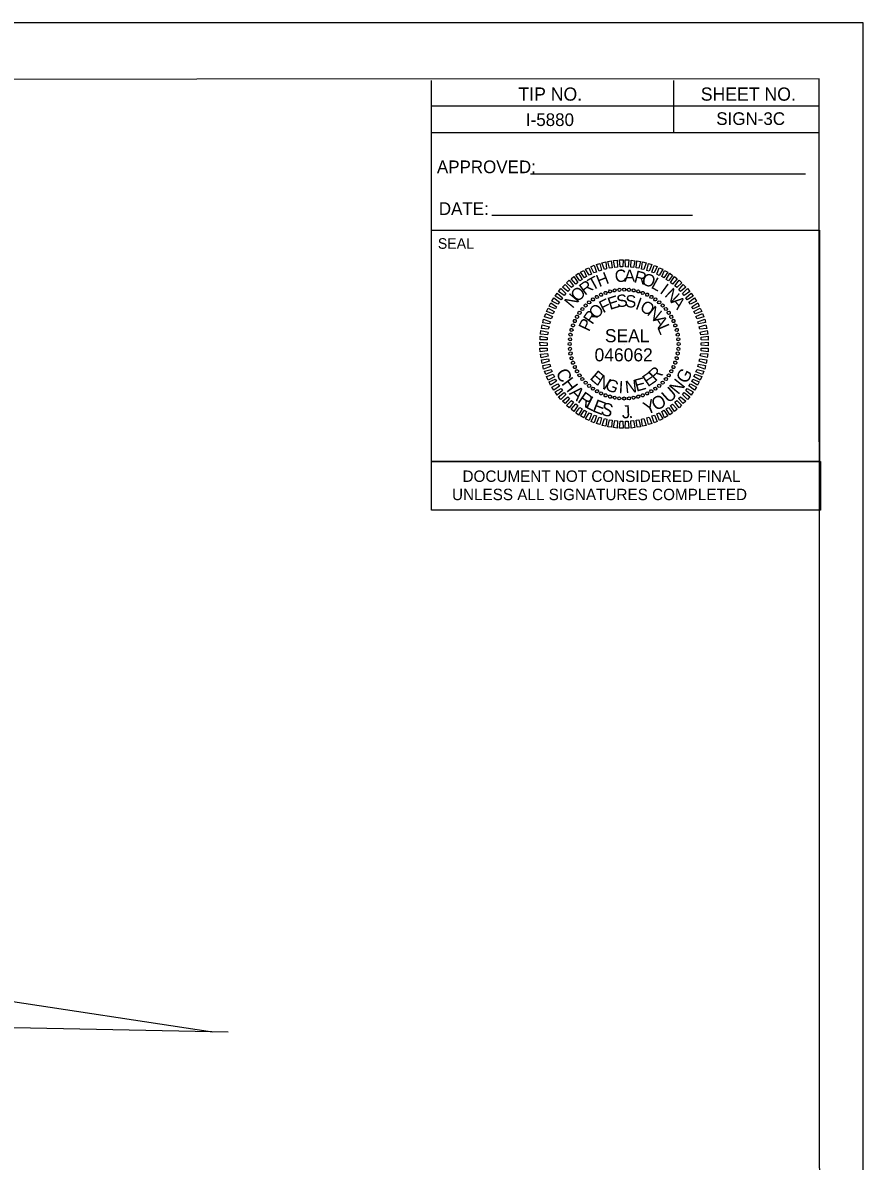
# Model space of a CAD drawing. Extents: x 1726582 to 1728895, y 538986 to 541550.
# Drawn here: x 1727860 to 1728265, y 539534 to 540082 of the extents above; entities that cross this region are included whole.
import ezdxf

# ---------------------------------------------------------------- set-up
doc = ezdxf.new("R2010")
doc.units = 0
for name, color, linetype in [('Default', 7, 'Continuous'), ('GSDIMS', 7, 'Continuous'), ('GSReplace', 7, 'Continuous'), ('Old_Level_2', 7, 'Continuous'), ('Old_Level_7', 7, 'Continuous'), ('Sheet Plot Border Outside CELL', 7, 'Continuous'), ('Sheet Sticker Exception Certification CELL', 7, 'Continuous')]:
    doc.layers.add(name, color=color, linetype=linetype)

msp = doc.modelspace()

# ---------------------------------------------------------------- linework, layer by layer
at = {"layer": 'GSDIMS'}
for p, q in [((1728056.85, 540029.09), (1728056.85, 540054.02)), ((1728173.5, 540029.08), (1728173.5, 540054.02)), ((1728056.85, 540041.82), (1728173.5, 540041.81)), ((1728173.5, 540041.81), (1728243.68, 540041.8)), ((1728056.85, 540029.09), (1728243.68, 540029.08)), ((1728056.85, 539981.95), (1728056.85, 540029.09))]:
    msp.add_line(p, q, dxfattribs=at)
for points in [[(1728243.5, 540054.9), (1726744.74, 540054.1), (1726745.3, 539004.97), (1728244.06, 539005.77)], [(1728056.85, 539981.95), (1728243.68, 539981.95), (1728243.68, 539870.64), (1728056.85, 539870.64)]]:
    msp.add_lwpolyline(points, close=True, dxfattribs=at)
at = {"layer": 'GSReplace'}
for p, q in [((1727827.39, 539614.8), (1727951.37, 539596.05)), ((1727958.9, 539595.93), (1727695.28, 539601.21))]:
    msp.add_line(p, q, dxfattribs=at)
at = {"layer": 'Old_Level_2'}
for p, q in [((1728138.52, 539950.97), (1728138.52, 539950.97)), ((1728140.6, 539951.85), (1728140.6, 539951.85)), ((1728142.78, 539952.51), (1728142.78, 539952.51)), ((1728145.08, 539952.97), (1728145.08, 539952.97)), ((1728147.32, 539953.32), (1728147.32, 539953.32)), ((1728149.62, 539953.42), (1728149.62, 539953.42)), ((1728151.92, 539953.3), (1728151.92, 539953.3)), ((1728154.18, 539952.97), (1728154.18, 539952.97)), ((1728156.38, 539952.54), (1728156.38, 539952.54)), ((1728158.59, 539951.85), (1728158.59, 539951.85)), ((1728160.7, 539950.94), (1728160.7, 539950.94)), ((1728131.03, 539945.72), (1728131.03, 539945.72)), ((1728132.73, 539947.32), (1728132.73, 539947.32)), ((1728134.54, 539948.65), (1728134.54, 539948.65)), ((1728136.5, 539949.89), (1728136.5, 539949.89)), ((1728162.75, 539949.93), (1728162.75, 539949.93)), ((1728164.66, 539948.66), (1728164.66, 539948.66)), ((1728166.51, 539947.28), (1728166.51, 539947.28)), ((1728168.16, 539945.74), (1728168.16, 539945.74)), ((1728126.84, 539940.31), (1728126.84, 539940.31)), ((1728128.11, 539942.21), (1728128.11, 539942.21)), ((1728129.49, 539944.07), (1728129.49, 539944.07)), ((1728169.76, 539944.04), (1728169.76, 539944.04)), ((1728171.1, 539942.23), (1728171.1, 539942.23)), ((1728172.34, 539940.27), (1728172.34, 539940.27)), ((1728124.92, 539936.14), (1728124.92, 539936.14)), ((1728125.83, 539938.25), (1728125.83, 539938.25)), ((1728173.42, 539938.25), (1728173.42, 539938.25)), ((1728174.29, 539936.17), (1728174.29, 539936.17)), ((1728123.47, 539929.48), (1728123.47, 539929.48)), ((1728123.8, 539931.73), (1728123.8, 539931.73)), ((1728124.23, 539933.94), (1728124.23, 539933.94)), ((1728174.96, 539933.98), (1728174.96, 539933.98)), ((1728175.41, 539931.69), (1728175.41, 539931.69)), ((1728175.77, 539929.45), (1728175.77, 539929.45)), ((1728123.35, 539927.17), (1728123.35, 539927.17)), ((1728123.45, 539924.88), (1728123.45, 539924.88)), ((1728149.61, 539927.16), (1728149.61, 539927.16)), ((1728175.74, 539924.85), (1728175.74, 539924.85)), ((1728175.86, 539927.15), (1728175.86, 539927.15)), ((1728123.8, 539922.63), (1728123.8, 539922.63)), ((1728124.26, 539920.34), (1728124.26, 539920.34)), ((1728124.92, 539918.15), (1728124.92, 539918.15)), ((1728174.29, 539918.18), (1728174.29, 539918.18)), ((1728174.98, 539920.39), (1728174.98, 539920.39)), ((1728175.42, 539922.59), (1728175.42, 539922.59)), ((1728125.8, 539916.08), (1728125.8, 539916.08)), ((1728126.88, 539914.06), (1728126.88, 539914.06)), ((1728172.38, 539914.01), (1728172.38, 539914.01)), ((1728173.39, 539916.07), (1728173.39, 539916.07)), ((1728128.11, 539912.09), (1728128.11, 539912.09)), ((1728129.45, 539910.28), (1728129.45, 539910.28)), ((1728131.05, 539908.59), (1728131.05, 539908.59)), ((1728168.18, 539908.61), (1728168.18, 539908.61)), ((1728169.72, 539910.26), (1728169.72, 539910.26)), ((1728171.1, 539912.11), (1728171.1, 539912.11)), ((1728132.7, 539907.05), (1728132.7, 539907.05)), ((1728134.55, 539905.67), (1728134.55, 539905.67)), ((1728136.46, 539904.39), (1728136.46, 539904.39)), ((1728138.52, 539903.38), (1728138.52, 539903.38)), ((1728140.62, 539902.48), (1728140.62, 539902.48)), ((1728142.83, 539901.78), (1728142.83, 539901.78)), ((1728156.43, 539901.81), (1728156.43, 539901.81)), ((1728158.61, 539902.48), (1728158.61, 539902.48)), ((1728160.69, 539903.35), (1728160.69, 539903.35)), ((1728162.71, 539904.43), (1728162.71, 539904.43)), ((1728164.68, 539905.67), (1728164.68, 539905.67)), ((1728166.48, 539907.01), (1728166.48, 539907.01)), ((1728145.04, 539901.35), (1728145.04, 539901.35)), ((1728147.29, 539901.03), (1728147.29, 539901.03)), ((1728149.59, 539900.91), (1728149.59, 539900.91)), ((1728151.89, 539901), (1728151.89, 539901)), ((1728154.14, 539901.35), (1728154.14, 539901.35))]:
    msp.add_line(p, q, dxfattribs=at)
for points in [[(1728145.09, 539964), (1728144.46, 539967.34), (1728146.23, 539967.58), (1728146.35, 539964.18)], [(1728147.7, 539964.31), (1728147.38, 539967.71), (1728149.11, 539967.68), (1728148.96, 539964.28)], [(1728150.21, 539964.3), (1728150.15, 539967.7), (1728151.88, 539967.68), (1728151.47, 539964.27)], [(1728152.83, 539964.19), (1728152.98, 539967.59), (1728154.71, 539967.31), (1728154.09, 539964)], [(1728130.54, 539958.99), (1728128.55, 539961.78), (1728130.16, 539962.65), (1728131.52, 539959.64)], [(1728132.76, 539960.29), (1728131.04, 539963.18), (1728132.65, 539963.94), (1728133.91, 539960.78)], [(1728135.05, 539961.42), (1728133.63, 539964.43), (1728135.19, 539965.09), (1728136.35, 539961.76)], [(1728137.59, 539962.3), (1728136.34, 539965.42), (1728137.95, 539965.92), (1728138.68, 539962.69)], [(1728140.09, 539963.03), (1728138.93, 539966.3), (1728140.71, 539966.7), (1728141.18, 539963.31)], [(1728142.59, 539963.65), (1728141.69, 539966.98), (1728143.42, 539967.17), (1728143.84, 539963.83)], [(1728155.35, 539963.82), (1728155.76, 539967.17), (1728157.49, 539966.94), (1728156.6, 539963.68)], [(1728158.02, 539963.29), (1728158.49, 539966.7), (1728160.27, 539966.31), (1728159.13, 539963.05)], [(1728160.54, 539962.65), (1728161.27, 539965.91), (1728162.9, 539965.41), (1728161.65, 539962.31)], [(1728162.91, 539961.75), (1728164.06, 539965.07), (1728165.53, 539964.47), (1728164.12, 539961.41)], [(1728165.28, 539960.8), (1728166.54, 539963.91), (1728168.17, 539963.2), (1728166.44, 539960.25)], [(1728167.71, 539959.64), (1728169.07, 539962.64), (1728170.65, 539961.78), (1728168.71, 539959.03)], [(1728124.24, 539954.38), (1728121.9, 539956.64), (1728123.13, 539957.92), (1728125.22, 539955.13)], [(1728126.3, 539956.04), (1728124.01, 539958.51), (1728125.4, 539959.63), (1728127.28, 539956.74)], [(1728128.26, 539957.64), (1728126.28, 539960.28), (1728127.62, 539961.29), (1728129.4, 539958.29)], [(1728169.77, 539958.26), (1728171.55, 539961.33), (1728172.93, 539960.25), (1728170.93, 539957.66)], [(1728171.94, 539956.73), (1728173.83, 539959.64), (1728175.21, 539958.52), (1728172.95, 539956.02)], [(1728173.96, 539955.15), (1728176.05, 539957.9), (1728177.33, 539956.67), (1728174.97, 539954.38)], [(1728119.22, 539948.49), (1728116.36, 539950.22), (1728117.33, 539951.75), (1728119.88, 539949.5)], [(1728120.75, 539950.51), (1728118, 539952.5), (1728119.12, 539953.88), (1728121.47, 539951.46)], [(1728122.54, 539952.52), (1728119.84, 539954.62), (1728121.13, 539955.85), (1728123.37, 539953.38)], [(1728175.87, 539953.35), (1728178.08, 539955.85), (1728179.35, 539954.61), (1728176.67, 539952.53)], [(1728177.74, 539951.5), (1728180.1, 539953.89), (1728181.22, 539952.5), (1728178.49, 539950.47)], [(1728179.34, 539949.49), (1728181.86, 539951.73), (1728182.88, 539950.23), (1728179.98, 539948.51)], [(1728116.47, 539944.1), (1728113.47, 539945.36), (1728114.22, 539946.99), (1728117.08, 539945.11)], [(1728117.68, 539946.37), (1728114.73, 539947.89), (1728115.75, 539949.37), (1728118.5, 539947.33)], [(1728180.74, 539947.37), (1728183.47, 539949.4), (1728184.49, 539947.85), (1728181.49, 539946.34)], [(1728182.14, 539945.09), (1728185.03, 539946.97), (1728185.74, 539945.36), (1728182.78, 539944.11)], [(1728114.46, 539939.36), (1728111.2, 539940.25), (1728111.85, 539941.88), (1728115.02, 539940.47)], [(1728115.46, 539941.68), (1728112.2, 539942.83), (1728112.96, 539944.46), (1728115.97, 539942.84)], [(1728183.22, 539942.86), (1728186.28, 539944.48), (1728186.99, 539942.82), (1728183.76, 539941.72)], [(1728184.2, 539940.42), (1728187.37, 539941.84), (1728187.97, 539940.23), (1728184.75, 539939.33)], [(1728113.08, 539934.32), (1728109.83, 539934.68), (1728110.17, 539936.46), (1728113.48, 539935.42)], [(1728113.72, 539936.84), (1728110.47, 539937.46), (1728110.8, 539939.19), (1728114.12, 539937.94)], [(1728185.08, 539937.93), (1728188.41, 539939.19), (1728188.75, 539937.47), (1728185.47, 539936.84)], [(1728185.76, 539935.43), (1728189.03, 539936.48), (1728189.38, 539934.71), (1728186.09, 539934.34)], [(1728112.49, 539929.13), (1728109.09, 539929.17), (1728109.17, 539930.9), (1728112.58, 539930.39)], [(1728112.71, 539931.64), (1728109.36, 539931.9), (1728109.54, 539933.68), (1728112.95, 539932.9)], [(1728186.27, 539932.93), (1728189.66, 539933.72), (1728189.84, 539931.94), (1728186.5, 539931.68)], [(1728186.63, 539930.42), (1728190.02, 539930.9), (1728190.15, 539929.12), (1728186.75, 539929.17)], [(1728112.49, 539926.51), (1728109.09, 539926.3), (1728109.06, 539928.08), (1728112.47, 539927.77)], [(1728112.59, 539923.9), (1728109.19, 539923.42), (1728109.06, 539925.2), (1728112.46, 539925.15)], [(1728186.72, 539925.2), (1728190.12, 539925.15), (1728190.04, 539923.42), (1728186.64, 539923.94)], [(1728186.73, 539927.81), (1728190.12, 539928.03), (1728190.15, 539926.25), (1728186.75, 539926.56)], [(1728112.94, 539921.4), (1728109.56, 539920.61), (1728109.37, 539922.38), (1728112.71, 539922.65)], [(1728113.46, 539918.9), (1728110.18, 539917.85), (1728109.84, 539919.62), (1728113.12, 539919.99)], [(1728186.13, 539920.01), (1728189.38, 539919.65), (1728189.04, 539917.86), (1728185.73, 539918.9)], [(1728186.5, 539922.68), (1728189.85, 539922.43), (1728189.67, 539920.64), (1728186.26, 539921.42)], [(1728114.13, 539916.4), (1728110.8, 539915.14), (1728110.46, 539916.86), (1728113.74, 539917.49)], [(1728115.01, 539913.9), (1728111.84, 539912.49), (1728111.24, 539914.1), (1728114.47, 539914.99)], [(1728115.99, 539911.46), (1728112.94, 539909.84), (1728112.23, 539911.5), (1728115.45, 539912.6)], [(1728183.75, 539912.64), (1728187.01, 539911.5), (1728186.25, 539909.86), (1728183.24, 539911.49)], [(1728184.75, 539914.96), (1728188.01, 539914.08), (1728187.36, 539912.45), (1728184.2, 539913.86)], [(1728185.49, 539917.49), (1728188.75, 539916.86), (1728188.41, 539915.13), (1728185.09, 539916.38)], [(1728117.08, 539909.23), (1728114.18, 539907.35), (1728113.47, 539908.96), (1728116.43, 539910.21)], [(1728118.48, 539906.96), (1728115.74, 539904.92), (1728114.72, 539906.47), (1728117.73, 539907.99)], [(1728181.53, 539907.95), (1728184.48, 539906.43), (1728183.46, 539904.95), (1728180.71, 539907)], [(1728182.74, 539910.22), (1728185.75, 539908.97), (1728184.99, 539907.33), (1728182.13, 539909.22)], [(1728119.87, 539904.84), (1728117.35, 539902.6), (1728116.33, 539904.09), (1728119.23, 539905.82)], [(1728121.48, 539902.82), (1728119.11, 539900.43), (1728117.99, 539901.82), (1728120.73, 539903.86)], [(1728123.34, 539900.97), (1728121.13, 539898.48), (1728119.86, 539899.71), (1728122.54, 539901.8)], [(1728176.67, 539901.8), (1728179.37, 539899.7), (1728178.09, 539898.48), (1728175.85, 539900.95)], [(1728178.46, 539903.82), (1728181.22, 539901.83), (1728180.09, 539900.45), (1728177.75, 539902.86)], [(1728180, 539905.83), (1728182.85, 539904.1), (1728181.88, 539902.57), (1728179.33, 539904.83)], [(1728125.25, 539899.18), (1728123.16, 539896.42), (1728121.88, 539897.65), (1728124.25, 539899.94)], [(1728127.27, 539897.59), (1728125.38, 539894.68), (1728124.01, 539895.81), (1728126.26, 539898.31)], [(1728129.44, 539896.06), (1728127.66, 539893), (1728126.28, 539894.07), (1728128.28, 539896.67)], [(1728170.95, 539896.68), (1728172.93, 539894.05), (1728171.59, 539893.03), (1728169.81, 539896.03)], [(1728172.91, 539898.28), (1728175.2, 539895.81), (1728173.81, 539894.69), (1728171.93, 539897.59)], [(1728174.97, 539899.94), (1728177.31, 539897.68), (1728176.08, 539896.4), (1728173.99, 539899.19)], [(1728131.5, 539894.68), (1728130.14, 539891.68), (1728128.56, 539892.54), (1728130.5, 539895.29)], [(1728133.93, 539893.52), (1728132.68, 539890.42), (1728131.04, 539891.12), (1728132.77, 539894.08)], [(1728136.3, 539892.57), (1728135.15, 539889.26), (1728133.68, 539889.86), (1728135.09, 539892.92)], [(1728138.67, 539891.67), (1728137.94, 539888.42), (1728136.31, 539888.91), (1728137.56, 539892.02)], [(1728141.19, 539891.04), (1728140.73, 539887.63), (1728138.94, 539888.02), (1728140.09, 539891.28)], [(1728143.87, 539890.51), (1728143.45, 539887.15), (1728141.72, 539887.38), (1728142.61, 539890.64)], [(1728156.62, 539890.68), (1728157.52, 539887.35), (1728155.8, 539887.16), (1728155.37, 539890.5)], [(1728159.12, 539891.3), (1728160.28, 539888.02), (1728158.51, 539887.62), (1728158.03, 539891.02)], [(1728161.62, 539892.02), (1728162.88, 539888.9), (1728161.27, 539888.4), (1728160.53, 539891.63)], [(1728164.17, 539892.9), (1728165.58, 539889.89), (1728164.02, 539889.24), (1728162.87, 539892.56)], [(1728166.45, 539894.04), (1728168.17, 539891.14), (1728166.56, 539890.38), (1728165.31, 539893.55)], [(1728168.67, 539895.33), (1728170.66, 539892.54), (1728169.05, 539891.68), (1728167.69, 539894.69)], [(1728146.38, 539890.13), (1728146.23, 539886.73), (1728144.5, 539887.01), (1728145.12, 539890.32)], [(1728149, 539890.02), (1728149.06, 539886.62), (1728147.33, 539886.65), (1728147.74, 539890.05)], [(1728151.51, 539890.01), (1728151.83, 539886.62), (1728150.1, 539886.64), (1728150.25, 539890.04)], [(1728154.12, 539890.32), (1728154.75, 539886.98), (1728152.98, 539886.74), (1728152.87, 539890.14)]]:
    msp.add_lwpolyline(points, close=True, dxfattribs=at)
for centre, major_axis in [((1728138.52, 539950.93), (-0.318, 0.682)), ((1728140.64, 539951.81), (-0.258, 0.708)), ((1728142.82, 539952.5), (-0.195, 0.727)), ((1728145.05, 539952.99), (-0.131, 0.742)), ((1728147.32, 539953.29), (-0.066, 0.75)), ((1728149.61, 539953.39), (0, 0.753)), ((1728151.89, 539953.29), (0.066, 0.75)), ((1728154.16, 539952.99), (0.131, 0.742)), ((1728156.39, 539952.5), (0.195, 0.727)), ((1728158.58, 539951.81), (0.258, 0.708)), ((1728160.69, 539950.93), (0.318, 0.682)), ((1728131.06, 539945.71), (-0.532, 0.532)), ((1728132.75, 539947.25), (-0.484, 0.577)), ((1728134.56, 539948.65), (-0.432, 0.617)), ((1728136.49, 539949.88), (-0.376, 0.652)), ((1728162.72, 539949.88), (0.376, 0.652)), ((1728164.65, 539948.65), (0.432, 0.617)), ((1728166.47, 539947.25), (0.484, 0.577)), ((1728168.15, 539945.71), (0.532, 0.532)), ((1728126.89, 539940.28), (-0.652, 0.376)), ((1728128.12, 539942.21), (-0.617, 0.432)), ((1728129.51, 539944.02), (-0.577, 0.484)), ((1728169.7, 539944.02), (0.577, 0.484)), ((1728171.09, 539942.21), (0.617, 0.432)), ((1728172.32, 539940.28), (0.652, 0.376)), ((1728124.27, 539933.95), (-0.727, 0.195)), ((1728124.96, 539936.13), (-0.708, 0.258)), ((1728125.84, 539938.25), (-0.682, 0.318)), ((1728173.38, 539938.25), (0.682, 0.318)), ((1728174.25, 539936.13), (0.708, 0.258)), ((1728174.94, 539933.95), (0.727, 0.195)), ((1728123.48, 539929.45), (-0.75, 0.066)), ((1728123.78, 539931.72), (-0.742, 0.131)), ((1728175.44, 539931.72), (0.742, 0.131)), ((1728175.73, 539929.45), (0.75, 0.066)), ((1728123.38, 539927.16), (-0.753, 0)), ((1728123.48, 539924.88), (-0.75, -0.066)), ((1728175.73, 539924.88), (0.75, -0.066)), ((1728175.83, 539927.16), (0.753, 0)), ((1728123.78, 539922.61), (-0.742, -0.131)), ((1728124.27, 539920.37), (-0.727, -0.195)), ((1728124.96, 539918.19), (-0.708, -0.258)), ((1728174.25, 539918.19), (0.708, -0.258)), ((1728174.94, 539920.37), (0.727, -0.195)), ((1728175.44, 539922.61), (0.742, -0.131)), ((1728125.84, 539916.08), (-0.682, -0.318)), ((1728126.89, 539914.05), (-0.652, -0.376)), ((1728128.12, 539912.12), (-0.617, -0.432)), ((1728171.09, 539912.12), (0.617, -0.432)), ((1728172.32, 539914.05), (0.652, -0.376)), ((1728173.38, 539916.08), (0.682, -0.318)), ((1728129.51, 539910.3), (-0.577, -0.484)), ((1728131.06, 539908.62), (-0.532, -0.532)), ((1728132.75, 539907.07), (-0.484, -0.577)), ((1728166.47, 539907.07), (0.484, -0.577)), ((1728168.15, 539908.62), (0.532, -0.532)), ((1728169.7, 539910.3), (0.577, -0.484)), ((1728134.56, 539905.68), (-0.432, -0.617)), ((1728136.49, 539904.45), (-0.376, -0.652)), ((1728138.52, 539903.39), (-0.318, -0.682)), ((1728140.64, 539902.52), (-0.258, -0.708)), ((1728142.82, 539901.83), (-0.195, -0.727)), ((1728145.05, 539901.33), (-0.131, -0.742)), ((1728147.32, 539901.03), (-0.066, -0.75)), ((1728149.61, 539900.93), (0, -0.753)), ((1728151.89, 539901.03), (0.066, -0.75)), ((1728154.16, 539901.33), (0.131, -0.742)), ((1728156.39, 539901.83), (0.195, -0.727)), ((1728158.58, 539902.52), (0.258, -0.708)), ((1728160.69, 539903.39), (0.318, -0.682)), ((1728162.72, 539904.45), (0.376, -0.652)), ((1728164.65, 539905.68), (0.432, -0.617))]:
    msp.add_ellipse(centre, major_axis=major_axis, ratio=0.999708, dxfattribs=at)
at = {"layer": 'Old_Level_7'}
for p, q in [((1728104.49, 540009.19), (1728237, 540009.19)), ((1728085.83, 539989.3), (1728182.53, 539989.3))]:
    msp.add_line(p, q, dxfattribs=at)
at = {"layer": 'Sheet Plot Border Outside CELL'}
msp.add_lwpolyline([(1728264.77, 540081.87), (1726581.86, 540081.87), (1726581.86, 538985.96), (1728264.77, 538985.96)], close=True, dxfattribs=at)
at = {"layer": 'Sheet Sticker Exception Certification CELL'}
for p, q in [((1728173.5, 540029.08), (1728173.5, 540054.02)), ((1728243.68, 540054.02), (1728243.68, 540054.02)), ((1728243.68, 540054.02), (1728243.68, 540054.02)), ((1728243.68, 540054.02), (1728243.68, 540054.02)), ((1728243.68, 540054.02), (1728243.68, 540054.02)), ((1728243.68, 540054.02), (1728243.68, 540054.02)), ((1728243.68, 540054.02), (1728243.68, 540054.02)), ((1728243.68, 540054.02), (1728243.68, 540054.02)), ((1728243.68, 540054.02), (1728243.68, 540054.02))]:
    msp.add_line(p, q, dxfattribs=at)
msp.add_lwpolyline([(1728056.85, 539870.64), (1728244.14, 539870.64), (1728244.14, 539847.16), (1728056.85, 539847.16)], close=True, dxfattribs=at)

# ---------------------------------------------------------------- texts
at = {"layer": 'Default'}
for s, rotation, p in [('C', 297.1998, (1728116.49, 539913.43)), ('G', 61.7997, (1728179.72, 539907.66)), ('H', 306.6436, (1728119.19, 539908.18)), ('N', 51.2288, (1728175.63, 539902.47)), ('A', 316.4834, (1728122.87, 539903.26)), ('R', 325.196, (1728126.8, 539899.49)), ('L', 332.5683, (1728130.54, 539896.79)), ('O', 30.0413, (1728164.96, 539894.74)), ('U', 41.4347, (1728171.06, 539898.41)), ('E', 338.7524, (1728133.92, 539894.91)), ('S', 345.7591, (1728137.97, 539893.23)), ('J', 3.0321, (1728148.57, 539891.31)), ('Y', 22.2425, (1728160.42, 539892.96)), ('.', 8.2139, (1728151.81, 539891.36))]:
    msp.add_text(s, height=6.27, rotation=rotation, dxfattribs=at).set_placement(p)
at = {"layer": 'Old_Level_2'}
for s, height, rotation, p in [('C', 5.9, 7.2198, (1728145.48, 539956.74)), ('A', 5.9, 0.0203, (1728149.61, 539957.13)), ('R', 5.9, 345.6211, (1728154, 539957)), ('R', 5.9, 36.0205, (1728130.69, 539950.37)), ('T', 5.9, 28.8197, (1728134.2, 539952.73)), ('H', 5.9, 21.6194, (1728137.57, 539954.51)), ('O', 5.9, 338.4211, (1728157.52, 539956.27)), ('L', 5.9, 331.2208, (1728162.15, 539954.42)), ('N', 5.9, 50.4235, (1728124.79, 539943.99)), ('O', 5.9, 43.2217, (1728127.14, 539947.06)), ('S', 5.9, 8.2556, (1728146.37, 539944.73)), ('I', 5.9, 324.0201, (1728166.43, 539951.98)), ('N', 5.9, 316.8189, (1728168.71, 539950.4)), ('O', 5.9, 45.6812, (1728136.07, 539938.8)), ('F', 5.9, 26.967, (1728139.46, 539941.94)), ('E', 5.9, 17.611, (1728142.78, 539943.57)), ('S', 5.9, 358.9004, (1728150.13, 539944.85)), ('I', 5.9, 340.1896, (1728154.64, 539944.19)), ('O', 5.9, 330.8335, (1728156.75, 539943.5)), ('N', 5.9, 321.4766, (1728160.29, 539941.47)), ('A', 5.9, 309.6171, (1728171.85, 539947.37)), ('R', 5.9, 55.0396, (1728134.28, 539936.2)), ('A', 5.9, 302.7602, (1728163.31, 539938.8)), ('P', 5.9, 64.3989, (1728132.67, 539932.83)), ('L', 5.9, 293.4008, (1728165.42, 539935.23)), ('SEAL', 6.273, 360, (1728140.33, 539928.05)), ('046062', 6.275, 360, (1728135.36, 539918.84)), ('E', 5.9, 319.2769, (1728132.74, 539910.5)), ('E', 5.9, 34.1241, (1728161, 539906.34)), ('R', 5.9, 43.4814, (1728164.67, 539908.86)), ('N', 5.9, 328.6339, (1728135.93, 539907.73)), ('G', 5.9, 337.9902, (1728139.94, 539905.45)), ('I', 5.9, 356.7012, (1728146.83, 539903.58)), ('N', 5.9, 6.0564, (1728150.33, 539903.48)), ('E', 5.9, 15.4117, (1728155.5, 539904.2))]:
    msp.add_text(s, height=height, rotation=rotation, dxfattribs=at).set_placement(p)
at = {"layer": 'Old_Level_7'}
for s, height, p in [('TIP NO.', 6.353, (1728098.68, 540044.36)), ('SHEET NO.', 6.353, (1728186.51, 540044.35)), ('SIGN-3C', 6.105, (1728193.99, 540032.66)), ('I-5880', 6.105, (1728102.3, 540032.15)), ('APPROVED:', 6.105, (1728059.43, 540009.45)), ('DATE:', 6.105, (1728060.35, 539989.33)), ('SEAL', 5.09, (1728059.87, 539973.05))]:
    msp.add_text(s, height=height, rotation=359.9949, dxfattribs=at).set_placement(p)
at = {"layer": 'Sheet Sticker Exception Certification CELL'}
for s, p in [('DOCUMENT NOT CONSIDERED FINAL', (1728071.75, 539860.8)), ('UNLESS ALL SIGNATURES COMPLETED', (1728066.69, 539852.01))]:
    msp.add_text(s, height=5.495, dxfattribs=at).set_placement(p)

doc.saveas('drawing.dxf')
